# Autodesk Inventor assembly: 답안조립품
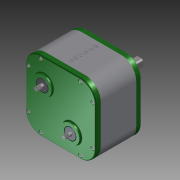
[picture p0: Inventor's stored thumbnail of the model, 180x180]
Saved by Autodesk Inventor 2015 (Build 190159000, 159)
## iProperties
Created: 2017-11
Part Number: 답안조립품
Document SubType Name: Assembly
Designer: SCD-A12
Mass: 2545.79 g
Surface Area: 2353.72 cm^2
Volume: 855.505 cm^3
Density: 2.97578 g/cm^3
Author: SCD-A12
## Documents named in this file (11)
- C:\Users\SCD-A12\Desktop\371107V1035\답안조립품.iam
- C:\Users\SCD-A12\Desktop\371107V1035\본체.ipt
- C:\Users\SCD-A12\Desktop\371107V1035\뒤커버.ipt
- C:\Users\SCD-A12\Desktop\371107V1035\메인축.ipt
- C:\Users\SCD-A12\Desktop\371107V1035\베어링 608.ipt
- C:\Users\SCD-A12\Desktop\371107V1035\베어링 6003.ipt
- C:\Users\SCD-A12\Desktop\371107V1035\볼트 M4.ipt
- C:\Users\SCD-A12\Desktop\371107V1035\서브축.ipt
- C:\Users\SCD-A12\Desktop\371107V1035\앞커버.ipt
- C:\Users\SCD-A12\Desktop\371107V1035\오일실 8 22 7.ipt
- C:\Users\SCD-A12\Desktop\371107V1035\오일실 17 32 8.ipt
